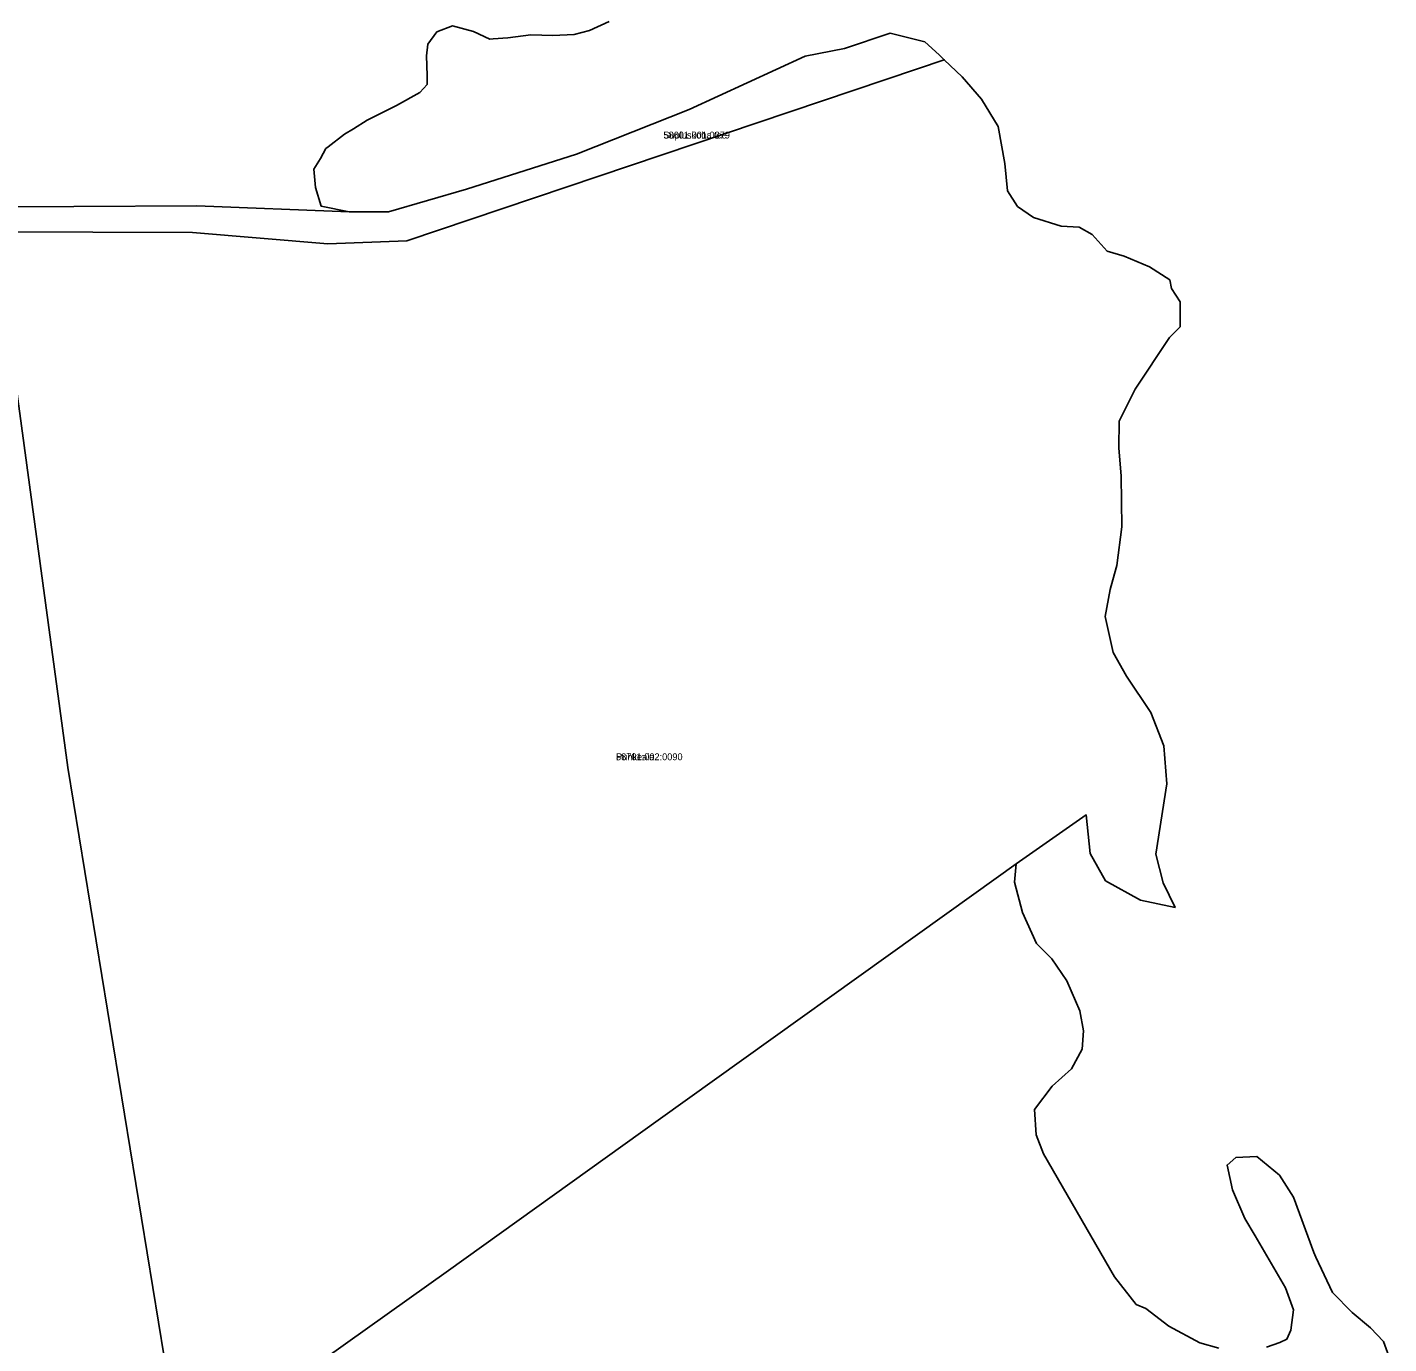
# Model space of a CAD drawing. Extents: x 663371 to 690098, y 6476568 to 6518353.
# Drawn here: x 687283.5 to 687580.1, y 6494578.3 to 6494865.1 of the extents above; entities that cross this region are included whole.
import ezdxf

# ---------------------------------------------------------------- set-up
doc = ezdxf.new("R2010")
doc.units = 0
for name, color, linetype in [('L_AADRESS', 7, 'Continuous'), ('PIIR', 7, 'Continuous'), ('TUNNUS', 7, 'Continuous')]:
    doc.layers.add(name, color=color, linetype=linetype)

msp = doc.modelspace()

# ---------------------------------------------------------------- linework, layer by layer
at = {"layer": 'PIIR'}
for points in [[(687410.22, 6494866.29), (687405.97, 6494864.38), (687402.62, 6494863.48), (687397.94, 6494863.3), (687393.16, 6494863.44), (687388.2, 6494862.76), (687384.95, 6494862.51), (687384.27, 6494862.46), (687380.71, 6494864.16), (687376.14, 6494865.36), (687372.71, 6494864.03), (687370.73, 6494861.38), (687370.42, 6494858.81), (687370.58, 6494854.52), (687370.59, 6494852.62), (687369.02, 6494850.85), (687363.92, 6494848.03), (687357.5, 6494844.83), (687354.52, 6494842.96), (687352.58, 6494841.74), (687348.99, 6494839), (687348.51, 6494838.63), (687347.32, 6494836.49), (687345.91, 6494834.14), (687346.23, 6494830.15), (687347.52, 6494826.07), (687353.57, 6494824.87), (687320.4, 6494826.19), (687186.34, 6494825.46)], [(687275.94, 6494820.53), (687319.47, 6494820.38), (687348.96, 6494817.92), (687366.15, 6494818.54), (687477.4, 6494855.98), (687483.26, 6494857.99), (687487.15, 6494854.25), (687491.37, 6494849.42), (687494.97, 6494843.42), (687496.44, 6494835.39), (687497.05, 6494829.42), (687499.19, 6494826.05), (687502.68, 6494823.64), (687508.71, 6494821.74), (687512.65, 6494821.5), (687515.49, 6494819.94), (687518.75, 6494816.31), (687522.44, 6494815.2), (687527.94, 6494812.9), (687532.36, 6494810.05), (687532.75, 6494808.19), (687534.65, 6494805.29), (687534.66, 6494799.83), (687532.33, 6494797.51), (687524.81, 6494786.21), (687521.33, 6494779.3), (687521.3, 6494773.45), (687521.81, 6494767.29), (687521.92, 6494756.25), (687520.87, 6494747.8), (687519.95, 6494744.71), (687519.37, 6494742.6), (687518.33, 6494736.76), (687520.06, 6494728.88), (687522.93, 6494723.7), (687528.25, 6494715.84), (687531.12, 6494708.55), (687531.77, 6494700.3), (687529.35, 6494684.97), (687530.93, 6494678.75), (687533.53, 6494673.35), (687525.98, 6494674.95), (687518.39, 6494679.17), (687515.02, 6494685.08), (687514.18, 6494693.52), (687498.94, 6494682.86), (687489.66, 6494676.22), (687420.9, 6494627), (687375.24, 6494594.32), (687317, 6494552.85), (687292.34, 6494703.81), (687278.51, 6494805.57)], [(687317, 6494552.85), (687375.24, 6494594.32), (687420.9, 6494627), (687489.66, 6494676.22), (687498.94, 6494682.86), (687498.54, 6494678.83), (687500.29, 6494672.29), (687503.37, 6494665.54), (687506.68, 6494662.14), (687509.96, 6494657.35), (687512.78, 6494650.85), (687513.6, 6494646.51), (687513.27, 6494642.46), (687510.95, 6494638.21), (687506.73, 6494634.43), (687502.93, 6494629.36), (687503.27, 6494623.86), (687504.84, 6494619.71), (687520.35, 6494592.92), (687525.07, 6494586.86), (687527.15, 6494586.01), (687532.21, 6494582.14), (687538.91, 6494578.57), (687543.04, 6494577.37)], [(687553.42, 6494577.61), (687556.34, 6494578.59), (687557.89, 6494579.35), (687558.74, 6494581.29), (687559.31, 6494585.69), (687557.58, 6494590.51), (687550.99, 6494601.84), (687548.71, 6494605.6), (687546.01, 6494611.87), (687544.87, 6494617.23), (687546.76, 6494618.89), (687551.38, 6494619.14), (687556.26, 6494615.03), (687559.34, 6494610.27), (687563.79, 6494598.2), (687564.23, 6494597.19), (687567.83, 6494589.51), (687572.14, 6494585.14), (687576.1, 6494581.77), (687578.97, 6494578.86), (687580.09, 6494575.61)]]:
    msp.add_lwpolyline(points, dxfattribs=at)
for points in [[(687353.57, 6494824.87), (687362.19, 6494824.84), (687379.14, 6494829.79), (687403.14, 6494837.43), (687427.65, 6494847.13), (687452.92, 6494858.75), (687461.52, 6494860.42), (687471.43, 6494863.74), (687478.98, 6494861.9), (687482.16, 6494859.05), (687483.26, 6494857.99), (687477.4, 6494855.98), (687366.15, 6494818.54), (687348.96, 6494817.92), (687319.47, 6494820.38), (687275.94, 6494820.53), (687187.19, 6494819.59), (687186.34, 6494825.46), (687320.4, 6494826.19)], [(687317, 6494552.85), (687308.31, 6494546.66), (687301.22, 6494541.61), (687298.44, 6494539.63), (687289.85, 6494533.49), (687280.59, 6494526.87), (687265.73, 6494516.24), (687253.23, 6494506.99), (687252.06, 6494506.15), (687244.03, 6494518.27), (687232, 6494511.1), (687187.19, 6494819.59), (687275.94, 6494820.53), (687278.51, 6494805.57), (687292.34, 6494703.81)]]:
    msp.add_lwpolyline(points, close=True, dxfattribs=at)

# ---------------------------------------------------------------- texts
at = {"layer": 'L_AADRESS'}
for s, p in [('Supluskoha tee', (687422.06, 6494840.83)), ('Puhkeala', (687411.74, 6494705.42))]:
    msp.add_text(s, height=1.5, dxfattribs=at).set_placement(p)
at = {"layer": 'TUNNUS'}
for s, p in [('58601:001:0379', (687422.06, 6494840.83)), ('58701:002:0090', (687411.74, 6494705.42))]:
    msp.add_text(s, height=1.5, dxfattribs=at).set_placement(p)

doc.saveas('drawing.dxf')
